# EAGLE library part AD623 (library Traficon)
Single Supply, Rail-to-Rail, Low Cost Instrumentation Amplifier
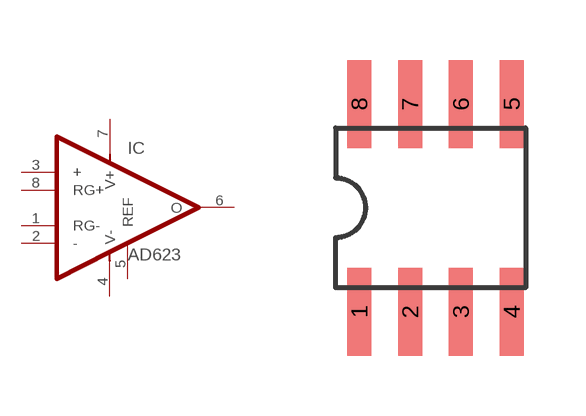
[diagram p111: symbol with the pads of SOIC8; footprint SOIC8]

Designator prefix IC

## AD623AR  [SOIC8]
1  RG-
2  -
3  +
4  V-
5  REF
6  O
7  V+
8  RG+

## Footprint SOIC8 (pad centres in mm)
Small Outline IC
smd 0.6 x 2.2: 1 -1.905,-2.6; 2 -0.635,-2.6; 3 0.635,-2.6; 4 1.905,-2.6; 5 1.905,2.6; 6 0.635,2.6; 7 -0.635,2.6; 8 -1.905,2.6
